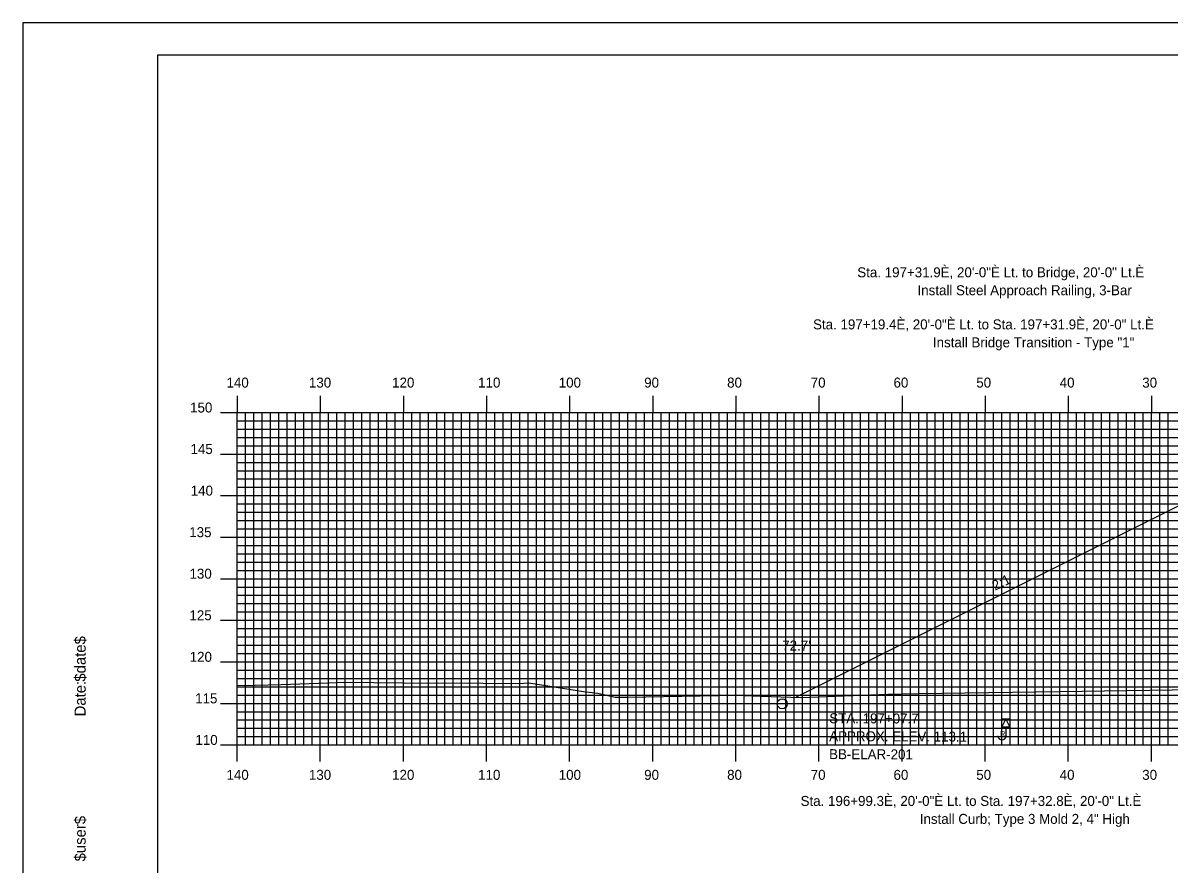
# Model space of a CAD drawing. Extents: x 1789730 to 1790074, y 442591 to 442811.
# Drawn here: x 1789730.4 to 1789868.3, y 442709.3 to 442810.5 of the extents above; entities that cross this region are included whole.
import ezdxf

# ---------------------------------------------------------------- set-up
doc = ezdxf.new("R2010")
doc.units = 0
for name, color, linetype in [('ANNOTATION', 7, 'Continuous'), ('BORDER', 7, 'Continuous'), ('BORING - REFUSAL', 7, 'Continuous'), ('D_Text_Standard', 7, 'Continuous'), ('H_V ANNOTATION', 7, 'Continuous'), ('MAJOR', 7, 'Continuous'), ('MINOR', 7, 'Continuous'), ('PLOT BOUNDARY', 7, 'Continuous'), ('S_Drainage_Invert', 7, 'Continuous'), ('S_Roadway_Centerline', 7, 'Continuous')]:
    doc.layers.add(name, color=color, linetype=linetype)

msp = doc.modelspace()

# ---------------------------------------------------------------- linework, layer by layer
at = {"layer": 'ANNOTATION'}
msp.add_line((1789873.18, 442754.28), (1789823.44, 442729.41), dxfattribs=at)
at = {"layer": 'BORDER'}
msp.add_lwpolyline([(1789746.58, 442596.67), (1790066.58, 442596.67), (1790066.58, 442806.67), (1789746.58, 442806.67)], close=True, dxfattribs=at)
at = {"layer": 'BORING - REFUSAL'}
for p, q in [((1789849.16, 442726.77), (1789848.2, 442726.77)), ((1789848.68, 442725.81), (1789848.68, 442724.75))]:
    msp.add_line(p, q, dxfattribs=at)
msp.add_lwpolyline([(1789848.68, 442726.77), (1789849.16, 442725.81), (1789848.2, 442725.81)], close=True, dxfattribs=at)
msp.add_arc((1789848.2, 442724.75), 0.485, 180, 0, dxfattribs=at)
at = {"layer": 'MAJOR'}
for p, q in [((1789756.18, 442765.67), (1789756.18, 442763.67)), ((1789766.18, 442765.67), (1789766.18, 442763.67)), ((1789776.18, 442765.67), (1789776.18, 442763.67)), ((1789786.18, 442765.67), (1789786.18, 442763.67)), ((1789796.18, 442765.67), (1789796.18, 442763.67)), ((1789806.18, 442765.67), (1789806.18, 442763.67)), ((1789816.18, 442765.67), (1789816.18, 442763.67)), ((1789826.18, 442765.67), (1789826.18, 442763.67)), ((1789836.18, 442765.67), (1789836.18, 442763.67)), ((1789846.18, 442765.67), (1789846.18, 442763.67)), ((1789856.18, 442765.67), (1789856.18, 442763.67)), ((1789866.18, 442765.67), (1789866.18, 442763.67)), ((1789754.18, 442763.67), (1789756.18, 442763.67)), ((1789756.18, 442763.67), (1790036.18, 442763.67)), ((1789756.18, 442723.67), (1789756.18, 442763.67)), ((1789756.18, 442723.67), (1789756.18, 442763.67)), ((1789756.18, 442763.67), (1790036.18, 442763.67)), ((1789766.18, 442723.67), (1789766.18, 442763.67)), ((1789776.18, 442723.67), (1789776.18, 442763.67)), ((1789786.18, 442723.67), (1789786.18, 442763.67)), ((1789796.18, 442723.67), (1789796.18, 442763.67)), ((1789806.18, 442723.67), (1789806.18, 442763.67)), ((1789816.18, 442723.67), (1789816.18, 442763.67)), ((1789826.18, 442723.67), (1789826.18, 442763.67)), ((1789836.18, 442723.67), (1789836.18, 442763.67)), ((1789846.18, 442723.67), (1789846.18, 442763.67)), ((1789856.18, 442723.67), (1789856.18, 442763.67)), ((1789866.18, 442723.67), (1789866.18, 442763.67)), ((1789754.18, 442758.67), (1789756.18, 442758.67)), ((1789756.18, 442758.67), (1790036.18, 442758.67)), ((1789754.18, 442753.67), (1789756.18, 442753.67)), ((1789756.18, 442753.67), (1790036.18, 442753.67)), ((1789754.18, 442748.67), (1789756.18, 442748.67)), ((1789756.18, 442748.67), (1790036.18, 442748.67)), ((1789754.18, 442743.67), (1789756.18, 442743.67)), ((1789756.18, 442743.67), (1790036.18, 442743.67)), ((1789754.18, 442738.67), (1789756.18, 442738.67)), ((1789756.18, 442738.67), (1790036.18, 442738.67)), ((1789754.18, 442733.67), (1789756.18, 442733.67)), ((1789756.18, 442733.67), (1790036.18, 442733.67)), ((1789754.18, 442728.67), (1789756.18, 442728.67)), ((1789756.18, 442728.67), (1790036.18, 442728.67)), ((1789754.18, 442723.67), (1789756.18, 442723.67)), ((1789756.18, 442723.67), (1790036.18, 442723.67)), ((1789756.18, 442723.67), (1790036.18, 442723.67)), ((1789756.18, 442721.66), (1789756.18, 442723.67)), ((1789766.18, 442721.66), (1789766.18, 442723.67)), ((1789776.18, 442721.66), (1789776.18, 442723.67)), ((1789786.18, 442721.66), (1789786.18, 442723.67)), ((1789796.18, 442721.66), (1789796.18, 442723.67)), ((1789806.18, 442721.66), (1789806.18, 442723.67)), ((1789816.18, 442721.66), (1789816.18, 442723.67)), ((1789826.18, 442721.66), (1789826.18, 442723.67)), ((1789836.18, 442721.66), (1789836.18, 442723.67)), ((1789846.18, 442721.66), (1789846.18, 442723.67)), ((1789856.18, 442721.66), (1789856.18, 442723.67)), ((1789866.18, 442721.66), (1789866.18, 442723.67))]:
    msp.add_line(p, q, dxfattribs=at)
at = {"layer": 'MINOR'}
for p, q in [((1789756.18, 442762.67), (1790036.18, 442762.67)), ((1789756.18, 442762.67), (1789758.19, 442762.67)), ((1789757.18, 442723.67), (1789757.18, 442763.67)), ((1789758.18, 442723.67), (1789758.18, 442763.67)), ((1789759.18, 442723.67), (1789759.18, 442763.67)), ((1789760.18, 442723.67), (1789760.18, 442763.67)), ((1789761.18, 442723.67), (1789761.18, 442763.67)), ((1789762.18, 442723.67), (1789762.18, 442763.67)), ((1789763.18, 442723.67), (1789763.18, 442763.67)), ((1789764.18, 442723.67), (1789764.18, 442763.67)), ((1789765.18, 442723.67), (1789765.18, 442763.67)), ((1789767.18, 442723.67), (1789767.18, 442763.67)), ((1789768.18, 442723.67), (1789768.18, 442763.67)), ((1789769.18, 442723.67), (1789769.18, 442763.67)), ((1789770.18, 442723.67), (1789770.18, 442763.67)), ((1789771.18, 442723.67), (1789771.18, 442763.67)), ((1789772.18, 442723.67), (1789772.18, 442763.67)), ((1789773.18, 442723.67), (1789773.18, 442763.67)), ((1789774.18, 442723.67), (1789774.18, 442763.67)), ((1789775.18, 442723.67), (1789775.18, 442763.67)), ((1789777.18, 442723.67), (1789777.18, 442763.67)), ((1789778.18, 442723.67), (1789778.18, 442763.67)), ((1789779.18, 442723.67), (1789779.18, 442763.67)), ((1789780.18, 442723.67), (1789780.18, 442763.67)), ((1789781.18, 442723.67), (1789781.18, 442763.67)), ((1789782.18, 442723.67), (1789782.18, 442763.67)), ((1789783.18, 442723.67), (1789783.18, 442763.67)), ((1789784.18, 442723.67), (1789784.18, 442763.67)), ((1789785.18, 442723.67), (1789785.18, 442763.67)), ((1789787.18, 442723.67), (1789787.18, 442763.67)), ((1789788.18, 442723.67), (1789788.18, 442763.67)), ((1789789.18, 442723.67), (1789789.18, 442763.67)), ((1789790.18, 442723.67), (1789790.18, 442763.67)), ((1789791.18, 442723.67), (1789791.18, 442763.67)), ((1789792.18, 442723.67), (1789792.18, 442763.67)), ((1789793.18, 442723.67), (1789793.18, 442763.67)), ((1789794.18, 442723.67), (1789794.18, 442763.67)), ((1789795.18, 442723.67), (1789795.18, 442763.67)), ((1789797.18, 442723.67), (1789797.18, 442763.67)), ((1789798.18, 442723.67), (1789798.18, 442763.67)), ((1789799.18, 442723.67), (1789799.18, 442763.67)), ((1789800.18, 442723.67), (1789800.18, 442763.67)), ((1789801.18, 442723.67), (1789801.18, 442763.67)), ((1789802.18, 442723.67), (1789802.18, 442763.67)), ((1789803.18, 442723.67), (1789803.18, 442763.67)), ((1789804.18, 442723.67), (1789804.18, 442763.67)), ((1789805.18, 442723.67), (1789805.18, 442763.67)), ((1789807.18, 442723.67), (1789807.18, 442763.67)), ((1789808.18, 442723.67), (1789808.18, 442763.67)), ((1789809.18, 442723.67), (1789809.18, 442763.67)), ((1789810.18, 442723.67), (1789810.18, 442763.67)), ((1789811.18, 442723.67), (1789811.18, 442763.67)), ((1789812.18, 442723.67), (1789812.18, 442763.67)), ((1789813.18, 442723.67), (1789813.18, 442763.67)), ((1789814.18, 442723.67), (1789814.18, 442763.67)), ((1789815.18, 442723.67), (1789815.18, 442763.67)), ((1789817.18, 442723.67), (1789817.18, 442763.67)), ((1789818.18, 442723.67), (1789818.18, 442763.67)), ((1789819.18, 442723.67), (1789819.18, 442763.67)), ((1789820.18, 442723.67), (1789820.18, 442763.67)), ((1789821.18, 442723.67), (1789821.18, 442763.67)), ((1789822.18, 442723.67), (1789822.18, 442763.67)), ((1789823.18, 442723.67), (1789823.18, 442763.67)), ((1789824.18, 442723.67), (1789824.18, 442763.67)), ((1789825.18, 442723.67), (1789825.18, 442763.67)), ((1789827.18, 442723.67), (1789827.18, 442763.67)), ((1789828.18, 442723.67), (1789828.18, 442763.67)), ((1789829.18, 442723.67), (1789829.18, 442763.67)), ((1789830.18, 442723.67), (1789830.18, 442763.67)), ((1789831.18, 442723.67), (1789831.18, 442763.67)), ((1789832.18, 442723.67), (1789832.18, 442763.67)), ((1789833.18, 442723.67), (1789833.18, 442763.67)), ((1789834.18, 442723.67), (1789834.18, 442763.67)), ((1789835.18, 442723.67), (1789835.18, 442763.67)), ((1789837.18, 442723.67), (1789837.18, 442763.67)), ((1789838.18, 442723.67), (1789838.18, 442763.67)), ((1789839.18, 442723.67), (1789839.18, 442763.67)), ((1789840.18, 442723.67), (1789840.18, 442763.67)), ((1789841.18, 442723.67), (1789841.18, 442763.67)), ((1789842.18, 442723.67), (1789842.18, 442763.67)), ((1789843.18, 442723.67), (1789843.18, 442763.67)), ((1789844.18, 442723.67), (1789844.18, 442763.67)), ((1789845.18, 442723.67), (1789845.18, 442763.67)), ((1789847.18, 442723.67), (1789847.18, 442763.67)), ((1789848.18, 442723.67), (1789848.18, 442763.67)), ((1789849.18, 442723.67), (1789849.18, 442763.67)), ((1789850.18, 442723.67), (1789850.18, 442763.67)), ((1789851.18, 442723.67), (1789851.18, 442763.67)), ((1789852.18, 442723.67), (1789852.18, 442763.67)), ((1789853.18, 442723.67), (1789853.18, 442763.67)), ((1789854.18, 442723.67), (1789854.18, 442763.67)), ((1789855.18, 442723.67), (1789855.18, 442763.67)), ((1789857.18, 442723.67), (1789857.18, 442763.67)), ((1789858.18, 442723.67), (1789858.18, 442763.67)), ((1789859.18, 442723.67), (1789859.18, 442763.67)), ((1789860.18, 442723.67), (1789860.18, 442763.67)), ((1789861.18, 442723.67), (1789861.18, 442763.67)), ((1789862.18, 442723.67), (1789862.18, 442763.67)), ((1789863.18, 442723.67), (1789863.18, 442763.67)), ((1789864.18, 442723.67), (1789864.18, 442763.67)), ((1789865.18, 442723.67), (1789865.18, 442763.67)), ((1789867.18, 442723.67), (1789867.18, 442763.67)), ((1789868.18, 442723.67), (1789868.18, 442763.67)), ((1789756.18, 442761.67), (1790036.18, 442761.67)), ((1789756.18, 442761.67), (1789758.19, 442761.67)), ((1789756.18, 442760.67), (1790036.18, 442760.67)), ((1789756.18, 442760.67), (1789758.19, 442760.67)), ((1789756.18, 442759.67), (1790036.18, 442759.67)), ((1789756.18, 442759.67), (1789758.19, 442759.67)), ((1789756.18, 442757.67), (1790036.18, 442757.67)), ((1789756.18, 442757.67), (1789758.19, 442757.67)), ((1789756.18, 442756.67), (1790036.18, 442756.67)), ((1789756.18, 442756.67), (1789758.19, 442756.67)), ((1789756.18, 442755.67), (1790036.18, 442755.67)), ((1789756.18, 442755.67), (1789758.19, 442755.67)), ((1789756.18, 442754.67), (1790036.18, 442754.67)), ((1789756.18, 442754.67), (1789758.19, 442754.67)), ((1789756.18, 442752.67), (1790036.18, 442752.67)), ((1789756.18, 442752.67), (1789758.19, 442752.67)), ((1789756.18, 442751.67), (1790036.18, 442751.67)), ((1789756.18, 442751.67), (1789758.19, 442751.67)), ((1789756.18, 442750.67), (1790036.18, 442750.67)), ((1789756.18, 442750.67), (1789758.19, 442750.67)), ((1789756.18, 442749.67), (1790036.18, 442749.67)), ((1789756.18, 442749.67), (1789758.19, 442749.67)), ((1789756.18, 442747.67), (1790036.18, 442747.67)), ((1789756.18, 442747.67), (1789758.19, 442747.67)), ((1789756.18, 442746.67), (1790036.18, 442746.67)), ((1789756.18, 442746.67), (1789758.19, 442746.67)), ((1789756.18, 442745.67), (1790036.18, 442745.67)), ((1789756.18, 442745.67), (1789758.19, 442745.67)), ((1789756.18, 442744.67), (1790036.18, 442744.67)), ((1789756.18, 442744.67), (1789758.19, 442744.67)), ((1789756.18, 442742.67), (1790036.18, 442742.67)), ((1789756.18, 442742.67), (1789758.19, 442742.67)), ((1789756.18, 442741.67), (1790036.18, 442741.67)), ((1789756.18, 442741.67), (1789758.19, 442741.67)), ((1789756.18, 442740.67), (1790036.18, 442740.67)), ((1789756.18, 442740.67), (1789758.19, 442740.67)), ((1789756.18, 442739.67), (1790036.18, 442739.67)), ((1789756.18, 442739.67), (1789758.19, 442739.67)), ((1789756.18, 442737.67), (1790036.18, 442737.67)), ((1789756.18, 442737.67), (1789758.19, 442737.67)), ((1789756.18, 442736.67), (1790036.18, 442736.67)), ((1789756.18, 442736.67), (1789758.19, 442736.67)), ((1789756.18, 442735.67), (1790036.18, 442735.67)), ((1789756.18, 442735.67), (1789758.19, 442735.67)), ((1789756.18, 442734.67), (1790036.18, 442734.67)), ((1789756.18, 442734.67), (1789758.19, 442734.67)), ((1789756.18, 442732.67), (1790036.18, 442732.67)), ((1789756.18, 442732.67), (1789758.19, 442732.67)), ((1789756.18, 442731.67), (1790036.18, 442731.67)), ((1789756.18, 442731.67), (1789758.19, 442731.67)), ((1789756.18, 442730.67), (1790036.18, 442730.67)), ((1789756.18, 442730.67), (1789758.19, 442730.67)), ((1789756.18, 442729.67), (1790036.18, 442729.67)), ((1789756.18, 442729.67), (1789758.19, 442729.67)), ((1789756.18, 442727.67), (1790036.18, 442727.67)), ((1789756.18, 442727.67), (1789758.19, 442727.67)), ((1789756.18, 442726.67), (1790036.18, 442726.67)), ((1789756.18, 442726.67), (1789758.19, 442726.67)), ((1789756.18, 442725.67), (1790036.18, 442725.67)), ((1789756.18, 442725.67), (1789758.19, 442725.67)), ((1789756.18, 442724.67), (1790036.18, 442724.67)), ((1789756.18, 442724.67), (1789758.19, 442724.67))]:
    msp.add_line(p, q, dxfattribs=at)
at = {"layer": 'PLOT BOUNDARY'}
msp.add_lwpolyline([(1789730.4, 442590.55), (1790070.4, 442590.55), (1790070.4, 442810.55), (1789730.4, 442810.55)], close=True, dxfattribs=at)
at = {"layer": 'S_Drainage_Invert'}
msp.add_circle((1789821.76, 442728.62), 0.6, dxfattribs=at)
at = {"layer": 'S_Roadway_Centerline'}
msp.add_lwpolyline([(1789756.18, 442730.83), (1789758.34, 442730.87), (1789761.47, 442730.94), (1789768.22, 442731.17), (1789768.97, 442731.23), (1789776.27, 442731.16), (1789783.88, 442731.12), (1789784.11, 442731.14), (1789785.74, 442731.09), (1789790.08, 442731.07), (1789791.26, 442731.13), (1789796.08, 442730.38), (1789797.84, 442730.08), (1789799.56, 442729.9), (1789801.66, 442729.4), (1789803.17, 442729.4), (1789816.23, 442729.65), (1789819.23, 442729.54), (1789823.99, 442729.39), (1789834.46, 442729.79), (1789836.16, 442729.83), (1789838.12, 442729.86), (1789855.11, 442730.11), (1789871.4, 442730.33)], dxfattribs=at)

# ---------------------------------------------------------------- texts
at = {"layer": 'ANNOTATION'}
for s, p in [('Sta. 197+31.9È, 20\'-0"È Lt. to Bridge, 20\'-0" Lt.È', (1789830.79, 442779.94)), ('Install Steel Approach Railing, 3-Bar', (1789838.04, 442777.78)), ('Sta. 197+19.4È, 20\'-0"È Lt. to Sta. 197+31.9È, 20\'-0" Lt.È', (1789825.47, 442773.67)), ('Install Bridge Transition - Type "1"', (1789839.89, 442771.51)), ('Sta. 196+99.3È, 20\'-0"È Lt. to Sta. 197+32.8È, 20\'-0" Lt.È', (1789823.97, 442716.33)), ('Install Curb; Type 3 Mold 2, 4" High', (1789838.31, 442714.17))]:
    msp.add_text(s, height=1.2, dxfattribs=at).set_placement(p)
msp.add_text('2:1', height=1.2, rotation=25.6852, dxfattribs=at).set_placement((1789847.36, 442742.21))
at = {"layer": 'BORDER'}
for s, p in [('$date$', (1789737.95, 442731.28)), ('Date:', (1789737.95, 442727.1)), ('$user$', (1789737.95, 442709.65))]:
    msp.add_text(s, height=1.339, rotation=90, dxfattribs=at).set_placement(p)
at = {"layer": 'BORING - REFUSAL'}
for s, p in [('STA. 197+07.7', (1789827.42, 442726.28)), ('APPROX. ELEV. 113.1', (1789827.41, 442724.12)), ('BB-ELAR-201', (1789827.4, 442721.96))]:
    msp.add_text(s, height=1.2, rotation=359.8142, dxfattribs=at).set_placement(p)
msp.add_text('R', height=0.64, dxfattribs=at).set_placement((1789847.97, 442724.69))
at = {"layer": 'D_Text_Standard'}
msp.add_text("72.7'", height=1.2, dxfattribs=at).set_placement((1789821.76, 442735.03))
at = {"layer": 'H_V ANNOTATION'}
for s, p in [('140', (1789754.89, 442766.67)), ('130', (1789764.81, 442766.67)), ('120', (1789774.82, 442766.67)), ('110', (1789785.17, 442766.67)), ('100', (1789794.87, 442766.67)), ('90', (1789805.15, 442766.67)), ('80', (1789815.13, 442766.67)), ('70', (1789825.19, 442766.67)), ('60', (1789835.15, 442766.67)), ('50', (1789845.11, 442766.67)), ('40', (1789855.15, 442766.67)), ('30', (1789865.08, 442766.67)), ('150', (1789750.51, 442763.67)), ('145', (1789750.56, 442758.67)), ('140', (1789750.59, 442753.67)), ('135', (1789750.41, 442748.67)), ('130', (1789750.44, 442743.67)), ('125', (1789750.43, 442738.67)), ('120', (1789750.46, 442733.67)), ('115', (1789751.12, 442728.67)), ('110', (1789751.15, 442723.67)), ('140', (1789754.89, 442719.47)), ('130', (1789764.81, 442719.47)), ('120', (1789774.82, 442719.47)), ('110', (1789785.17, 442719.47)), ('100', (1789794.87, 442719.47)), ('90', (1789805.15, 442719.47)), ('80', (1789815.13, 442719.47)), ('70', (1789825.19, 442719.47)), ('60', (1789835.15, 442719.47)), ('50', (1789845.11, 442719.47)), ('40', (1789855.15, 442719.47)), ('30', (1789865.08, 442719.47))]:
    msp.add_text(s, height=1.2, dxfattribs=at).set_placement(p)
at = {"layer": 'MAJOR'}
msp.add_text('-', height=0.012, dxfattribs=at).set_placement((1789756.17, 442723.67))
at = {"layer": 'S_Roadway_Centerline'}
for s, p in [('C', (1789768.96, 442731.23)), ('C', (1789768.96, 442731.23)), ('L', (1789768.97, 442731.22)), ('L', (1789768.97, 442731.22))]:
    msp.add_text(s, height=0.0146, dxfattribs=at).set_placement(p)

doc.saveas('drawing.dxf')
